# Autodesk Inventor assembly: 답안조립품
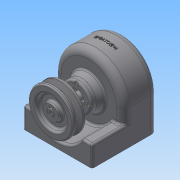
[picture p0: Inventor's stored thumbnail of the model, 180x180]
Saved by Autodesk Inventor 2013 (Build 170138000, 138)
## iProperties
Created: 2015-02
Part Number: 답안조립품
Document SubType Name: Assembly
Designer: Administrator
Author: Administrator
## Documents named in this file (10)
- C:\Documents and Settings\Administrator\바탕 화면\450214V1028\답안조립품.iam
- C:\Documents and Settings\Administrator\바탕 화면\450214V1028\1-본체.ipt
- C:\Documents and Settings\Administrator\바탕 화면\450214V1028\베어링 6001.ipt
- C:\Documents and Settings\Administrator\바탕 화면\450214V1028\축.ipt
- C:\Documents and Settings\Administrator\바탕 화면\450214V1028\키4x4.ipt
- C:\Documents and Settings\Administrator\바탕 화면\450214V1028\키5x5.ipt
- C:\Documents and Settings\Administrator\바탕 화면\450214V1028\스퍼기어.ipt
- C:\Documents and Settings\Administrator\바탕 화면\450214V1028\축커버.ipt
- C:\Documents and Settings\Administrator\바탕 화면\450214V1028\M3x0.5.ipt
- C:\Documents and Settings\Administrator\바탕 화면\450214V1028\4-V-벨트풀리.ipt
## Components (6 placed, 3 different names)
1. 1-본체:1
2. 4-V-벨트풀리:1
3. M3x0.5:1
4. M3x0.5:2
5. M3x0.5:3
6. M3x0.5:4
